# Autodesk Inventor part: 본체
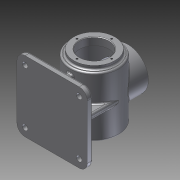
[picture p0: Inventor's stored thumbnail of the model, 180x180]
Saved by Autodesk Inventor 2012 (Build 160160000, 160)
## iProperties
Created: 2015-07
Part Number: 본체
Material: Default
Document SubType Name: Modeling
Designer: Owner
Density: 1 g/cm^3
Author: Owner
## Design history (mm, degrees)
sketch "스케치1"
  geometry: C1 r 45 at (0, 0); 1 further point
  constraints: 1 centre point, 1 coincident
  dimensions: "d0" = 90 diameter of C1
extrude "돌출1" new body sketch "스케치1" stored distance "d1" = 110; taper "d2" = 0 deg
sketch "스케치2"
  geometry: C1 r 45 at (0, 0) reference; C2 r 38 at (0, 0)
  constraints: 1 centre point, 1 coincident
  dimensions: "d3" = 76 diameter of C2
extrude "돌출2" join sketch "스케치2" distance "d4" = 7; taper "d5" = 0 deg
sketch "스케치3"
  geometry: C1 r 40 at (0, 0); 1 further point
  constraints: 1 centre point, 1 coincident
  dimensions: "d6" = 80 diameter of C1
extrude "돌출3" cut sketch "스케치3" stored distance "d7" = 96; taper "d8" = 0 deg
sketch "스케치4"
  geometry: C1 r 38 at (0, 0) reference; C2 r 27 at (0, 0)
  constraints: 1 centre point, 1 coincident
  dimensions: "d9" = 54 diameter of C2
extrude "돌출4" cut sketch "스케치4" stored distance "d10" = 96; taper "d11" = 0 deg
node "작업 평면1"
sketch "스케치5"
  geometry: L1 (65, 65)-(-65, 65); L2 (-65, 65)-(-65, -65); L3 (-65, -65)-(65, -65); L4 (65, -65)-(65, 65); L5 (65, -65)-(-65, 65); L6 (65, 65)-(-65, -65); 2 further points
  constraints: 12 end point, 2 parallel, 1 coincident, 1 horizontal, 1 midpoint, 1 perpendicular
  dimensions: "d13" = 130 distance of L3.end L2.end; "d14" = 130 distance of L2.end L1.end
extrude "돌출5" join sketch "스케치5" distance "d15" = 10; taper "d16" = 0 deg
sketch "스케치6"
  geometry: L1 (45, 0)-(45, -68); L2 (-45, 0)-(-45, -68); L3 (-65, -68)-(65, -68) reference; A1 r 45 centre (0, 0) between (-45, 0) and (45, 0) reference; 1 further point
  constraints: 4 end point, 2 point on circle, 2 point on line, 2 tangent, 1 parallel, 1 vertical
extrude "돌출6" join sketch "스케치6" stored distance "d17" = 10; taper "d18" = 0 deg
fillet "모깎기1" dims "d23" = 15
node "작업 평면2"
sketch "스케치8"
  geometry: C1 r 38 at (0, 0); 1 further point
  constraints: 1 centre point, 1 coincident
  dimensions: "d25" = 76 diameter of C1
extrude "돌출8" join sketch "스케치8" stored distance "d26" = 10; taper "d27" = 0 deg
sketch "스케치9"
  geometry: C1 r 27 at (0, 0); 1 further point
  constraints: 1 centre point, 1 coincident
  dimensions: "d28" = 54 diameter of C1
extrude "돌출9" cut sketch "스케치9" stored distance "d29" = 10; taper "d30" = 0 deg
sketch "스케치10"
  geometry: 2 further points
  constraints: 1 horizontal alignment
  dimensions: "d31" = 32 distance of point (0, 0) point (-32, 0)
hole "구멍1" sketch "스케치10" at (-32, 0) diameter "d32" = 3.242; stored, may be unused: countersink angle "d36" = 90 deg, drill point angle "d38" = 118 deg; dims "d33" = 8, "d34" = 4, "d35" = 2, "d37" = 10
sketch "스케치11"
  geometry: C1 r 27 at (0, 0) reference; 1 further point
  constraints: 1 vertical alignment
  dimensions: "d42" = 32 distance of C1.centre point (0, 32)
hole "구멍2" sketch "스케치11" at (0, 32) diameter "d43" = 3.242; stored, may be unused: countersink angle "d47" = 90 deg, drill point angle "d49" = 118 deg; dims "d44" = 8, "d45" = 4, "d46" = 2, "d48" = 10
sketch "스케치12"
  geometry: C1 r 7.5 at (-50, 50); A1 r 15 centre (-50, 50) between (-50, 65) and (-65, 50) reference; 1 further point
  constraints: 1 centre point, 1 coincident
  dimensions: "d53" = 15 diameter of C1
extrude "돌출10" join sketch "스케치12" distance "d54" = 3; taper "d55" = 0 deg
sketch "스케치13"
  geometry: C1 r 7.5 at (0, 0) reference; C2 r 5 at (0, 0); 1 further point
  constraints: 1 centre point, 1 coincident
  dimensions: "d56" = 10 diameter of C2
extrude "돌출11" cut sketch "스케치13" stored distance "d57" = 3; taper "d58" = 0 deg
fillet "모깎기2" dims "d59" = 3
chamfer "모따기1" distance "d66" = 1; stored, may be unused: second distance "d67" = 2, angle "d68" = 45 deg
fillet "모깎기3" dims "d69" = 3
fillet "모깎기4" dims "d70" = 3
sketch "스케치14"
  geometry: L1 (-5, 45)-(5, 45); L2 (5, 45)-(5, -45); L3 (5, -45)-(-5, -45); L4 (-5, -45)-(-5, 45); L5 (-5, 45)-(5, -45); 2 further points
  constraints: 10 end point, 2 parallel, 1 coincident, 1 horizontal, 1 midpoint, 1 perpendicular
  dimensions: "d71" = 10 distance of L1.start L1.end; "d72" = 90 distance of L3.end L1.start
extrude "돌출12" join sketch "스케치14" stored distance "d73" = 3; taper "d74" = 0 deg
fillet "모깎기5" dims "d75" = 3
fillet "모깎기6" dims "d76" = 3
fillet "모깎기7" dims "d77" = 3
sketch "스케치15"
  geometry: C1 r 42 at (0, 0) reference; 2 further points
  constraints: 3 coincident, 1 other
feature "엠보싱1" sketch "스케치15" dims "d78" = 0.5, "d79" = 0
fillet "모깎기8" dims "d80" = 3
fillet "모깎기9" dims "d81" = 3
node "솔리드1"
pattern_circular "원형 패턴1" dims angle "d40" = 360 deg
pattern_circular "원형 패턴2" dims angle "d51" = 360 deg
pattern_linear "직사각형 패턴1"
other parameters: "d12" = -78
